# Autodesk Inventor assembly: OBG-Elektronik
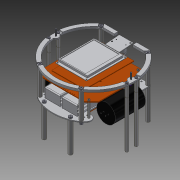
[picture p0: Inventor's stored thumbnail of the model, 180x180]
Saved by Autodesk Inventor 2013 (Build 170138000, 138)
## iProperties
Created: 2012-08
Part Number: OBG-Elektronik
Document SubType Name: Assembly
Designer: rYan
Mass: 1020.23 g
Surface Area: 2037.74 cm^2
Volume: 481.002 cm^3
Density: 2.12105 g/cm^3
Author: rYan
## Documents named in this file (23)
- D:\SVN\2013\Inventor\Elektronik\OBG-Elektronik.iam
- D:\SVN\2013\Inventor\Elektronik\Elektronikhalter.ipt
- D:\SVN\2013\Inventor\Elektronik\Kondensatorhalter.ipt
- D:\SVN\2013\Inventor\Kaufteile\Abstandsbolzen Typ A M4-65mm.ipt
- E:\Tigers SVN\mechanik\2013\Inventor\Kaufteile\Abstandsbolzen Typ A.ipt
- D:\SVN\2013\Inventor\Kaufteile\Kondensator 40x65.ipt
- D:\SVN\2013\Inventor\Kaufteile\Abstandsbolzen Typ A M2.5-20mm-SW4.ipt
- D:\SVN\2013\Inventor\Kaufteile\Abstandsbolzen Typ A M2.5-30mm-SW4.ipt
- D:\SVN\2013\Inventor\Inhaltscenter\de-DE\DIN 7984\DIN 7984 - M3 x 6.ipt
- D:\SVN\2013\Inventor\Elektronik\UBG-Mainboard.iam
- D:\SVN\2013\Inventor\Elektronik\Kickerboard.ipt
- D:\SVN\2013\Inventor\Kaufteile\Akku 2S1P.ipt
- E:\Tigers SVN\mechanik\2013\Inventor\Kaufteile\Abstandsbolzen Typ B.ipt
- D:\SVN\2013\Inventor\Ring.ipt
- D:\SVN\2013\Inventor\Kaufteile\Abstandsbolzen Typ A M3-100mm.ipt
- D:\SVN\2013\Inventor\Inhaltscenter\de-DE\DIN 7984\DIN 7984 - M3 x 16.ipt
- D:\SVN\2013\Inventor\Kaufteile\Abstandsbolzen Typ B M3-22mm.ipt
- D:\SVN\2013\Inventor\Kaufteile\Abstandsbolzen Typ B M4-55mm.ipt
- D:\SVN\2013\Inventor\Inhaltscenter\de-DE\ISO 10511\ISO 10511 - M4.ipt
- D:\SVN\2013\Inventor\Kaufteile\Abstandsbolzen Typ B M3-10mm.ipt
- D:\SVN\2013\Inventor\Inhaltscenter\en-US\DIN 7984\DIN 7984 - M4 x 6.ipt
- D:\SVN\2013\Inventor\Inhaltscenter\en-US\DIN 7984\DIN 7984 - M3 x 6.ipt
- D:\SVN\2013\Inventor\Inhaltscenter\en-US\ISO 4762(1)\ISO 4762 - M2,5 x 6DIN EN ISO.ipt
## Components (68 placed, 19 different names)
1. Elektronikhalter:1 — Passend:1, Passend:2, Passend:3, Passend:4, Passend:5, Passend:6, Passend:9, Passend:10, Passend:11, Passend:14, Passend:21, Passend:22, Passend:23, Passend:24, Passend:39, Passend:40, Passend:43, Passend:44, Passend:52, Passend:54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
2. UBG-Mainboard:1 [sub-assembly] — Passend:157, Passend:158, Passend:159, Passend:168, Passend:169, Passend:170, Passend:171
3. Kondensator 40x65:2 — Passend:16, Fluchtend:1, Fluchtend:3
4. Kondensator 40x65:1 — Passend:15, Fluchtend:1, Fluchtend:2, Fluchtend:3
5. Kickerboard:1 — Passend:102, Passend:103, Passend:104, Mate:255
6. Akku 2S1P:1 — Passend:113, Passend:114
7. Akku 2S1P:2 — Passend:115, Passend:116
8. Ring:1 — Passend:192, Passend:194, Passend:196, Passend:198, Passend:207, Passend:208, Passend:209, Passend:210, Passend:211, Passend:212, Passend:213, Passend:214, Passend:216, Passend:218, Passend:220, Passend:222, Passend:224, Passend:226, Passend:235, Passend:236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
9. DIN 7984 M3 x 16:1 — Passend:224
10. DIN 7984 M3 x 16:2 — Passend:226
11. DIN EN ISO 10511 M4:1 — Passend:243
12. DIN EN ISO 10511 M4:2 — Passend:245
13. Abstandsbolzen Typ B M3-10mm:25 — Mate:246, Mate:252
14. Abstandsbolzen Typ B M3-10mm:26 — Mate:247, Mate:253
15. Abstandsbolzen Typ B M3-10mm:27 — Mate:248, Mate:251
16. Abstandsbolzen Typ B M3-10mm:28 — Mate:249, Mate:250
17. Abstandsbolzen Typ A M4-65mm:2 — Passend:10, Passend:14, Fluchtend:6
18. Abstandsbolzen Typ A M4-65mm:4 — Passend:9, Passend:11, Fluchtend:6
19. Abstandsbolzen Typ A M4-65mm:15 — Passend:144, Passend:145, Fluchtend:7
20. Abstandsbolzen Typ A M4-65mm:16 — Passend:143, Passend:146, Fluchtend:7
21. DIN 7984 M4 x 6:5
22. DIN 7984 M4 x 6:6 — Passend:152
23. Abstandsbolzen Typ A M2.5-30mm-SW4:19 — Passend:160, Passend:163
24. DIN EN ISO 4762 M2,5 x 6:10 — Passend:169, Passend:171
25. DIN EN ISO 4762 M2,5 x 6:9 — Passend:165, Passend:166
26. Abstandsbolzen Typ A M2.5-30mm-SW4:20 — Passend:161, Passend:162
27. DIN EN ISO 4762 M2,5 x 6:8 — Passend:168, Passend:170
28. DIN EN ISO 4762 M2,5 x 6:7 — Passend:164, Passend:167
29. Abstandsbolzen Typ A M2.5-30mm-SW4:12 — Passend:40, Passend:44, Passend:112, Passend:157, Passend:159
30. DIN EN ISO 4762 M2,5 x 6:6 — Passend:54
31. DIN EN ISO 4762 M2,5 x 6:5 — Passend:112
32. Abstandsbolzen Typ A M2.5-30mm-SW4:11 — Passend:39, Passend:43, Passend:110, Passend:158
33. DIN EN ISO 4762 M2,5 x 6:4 — Passend:52
34. DIN EN ISO 4762 M2,5 x 6:3 — Passend:110
35. Abstandsbolzen Typ A M2.5-20mm-SW4:7 — Passend:22, Passend:24, Fluchtend:4, Passend:114
36. DIN EN ISO 4762 M2,5 x 6:1 — Passend:84
37. Abstandsbolzen Typ A M2.5-20mm-SW4:8 — Passend:21, Passend:23, Fluchtend:4, Passend:116
38. DIN EN ISO 4762 M2,5 x 6:2 — Passend:86
39. Kondensatorhalter:1 — Passend:4, Passend:5, Passend:6, Passend:16
40. DIN 7984 M3 x 6:2 — Passend:62
41. DIN 7984 M3 x 6:3 — Passend:64
42. Kondensatorhalter:2 — Passend:1, Passend:2, Passend:3, Passend:15, Fluchtend:2, Passend:60, Passend:62, Passend:64, Passend:70
43. DIN 7984 M3 x 6:1 — Passend:60
44. DIN 7984 M3 x 6:4 — Passend:70
45. Abstandsbolzen Typ B M4-55mm:21 — Passend:227, Passend:233, Fluchtend:15
46. Abstandsbolzen Typ B M4-55mm:22 — Passend:228, Passend:234, Fluchtend:15
47. Abstandsbolzen Typ B M4-55mm:23 — Passend:229, Passend:231, Passend:236, Passend:237, Fluchtend:14
48. Abstandsbolzen Typ B M4-55mm:24 — Passend:230, Passend:232, Passend:235, Fluchtend:14
49. DIN 7984 M4 x 6:1 — Passend:192, Passend:240
50. DIN 7984 M4 x 6:2 — Passend:194, Passend:241
51. DIN 7984 M4 x 6:3 — Passend:196, Passend:238
52. DIN 7984 M4 x 6:4 — Passend:198, Passend:239
53. Abstandsbolzen Typ B M3-22mm:13 — Passend:199, Passend:200, Fluchtend:8, Passend:207, Passend:214, Fluchtend:12
54. Abstandsbolzen Typ B M3-22mm:14 — Passend:201, Passend:202, Fluchtend:9, Passend:208, Passend:213, Fluchtend:12
55. Abstandsbolzen Typ B M3-22mm:15 — Passend:205, Passend:206, Fluchtend:11, Passend:209, Passend:212, Fluchtend:13
56. Abstandsbolzen Typ B M3-22mm:16 — Passend:203, Passend:204, Fluchtend:10, Passend:210, Passend:211, Fluchtend:13
57. Abstandsbolzen Typ A M3-100mm:23 — Passend:199, Passend:200, Fluchtend:8
58. Abstandsbolzen Typ A M3-100mm:24 — Passend:201, Passend:202, Fluchtend:9
59. Abstandsbolzen Typ A M3-100mm:25 — Passend:205, Passend:206, Fluchtend:11
60. Abstandsbolzen Typ A M3-100mm:26 — Passend:203, Passend:204, Fluchtend:10
61. DIN 7984 M3 x 6:5 — Passend:218
62. DIN 7984 M3 x 6:6 — Passend:220
63. DIN 7984 M3 x 6:7 — Passend:222
64. DIN 7984 M3 x 6:8 — Passend:216
65. DIN 7984 M3 x 6:9 — Mate:255
66. DIN 7984 M3 x 6:10
67. DIN 7984 M3 x 6:11
68. DIN 7984 M3 x 6:12
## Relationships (123: Mate 109, Flush 14)
- Passend:1 [Mate]: Elektronikhalter:1 ↔ Kondensatorhalter:2
- Passend:2 [Mate]: Elektronikhalter:1 ↔ Kondensatorhalter:2
- Passend:3 [Mate]: Elektronikhalter:1 ↔ Kondensatorhalter:2
- Passend:4 [Mate]: Elektronikhalter:1 ↔ Kondensatorhalter:1
- Passend:5 [Mate]: Elektronikhalter:1 ↔ Kondensatorhalter:1
- Passend:6 [Mate]: Elektronikhalter:1 ↔ Kondensatorhalter:1
- Passend:9 [Mate]: Elektronikhalter:1 ↔ Abstandsbolzen Typ A M4-65mm:4
- Passend:10 [Mate]: Elektronikhalter:1 ↔ Abstandsbolzen Typ A M4-65mm:2
- Passend:11 [Mate]: Elektronikhalter:1 ↔ Abstandsbolzen Typ A M4-65mm:4
- Passend:14 [Mate]: Elektronikhalter:1 ↔ Abstandsbolzen Typ A M4-65mm:2
- Passend:15 [Mate]: Kondensator 40x65:1 ↔ Kondensatorhalter:2
- Passend:16 [Mate]: Kondensator 40x65:2 ↔ Kondensatorhalter:1
- Fluchtend:1 [Flush]: Kondensator 40x65:2 ↔ Kondensator 40x65:1
- Fluchtend:2 [Flush]: Kondensator 40x65:1 ↔ Kondensatorhalter:2
- Fluchtend:3 [Flush]: Kondensator 40x65:2 ↔ Kondensator 40x65:1
- Passend:21 [Mate]: Elektronikhalter:1 ↔ Abstandsbolzen Typ A M2.5-20mm-SW4:8
- Passend:22 [Mate]: Elektronikhalter:1 ↔ Abstandsbolzen Typ A M2.5-20mm-SW4:7
- Passend:23 [Mate]: Elektronikhalter:1 ↔ Abstandsbolzen Typ A M2.5-20mm-SW4:8
- Passend:24 [Mate]: Elektronikhalter:1 ↔ Abstandsbolzen Typ A M2.5-20mm-SW4:7
- Fluchtend:4 [Flush]: Abstandsbolzen Typ A M2.5-20mm-SW4:7 ↔ Abstandsbolzen Typ A M2.5-20mm-SW4:8
- Passend:39 [Mate]: Elektronikhalter:1 ↔ Abstandsbolzen Typ A M2.5-30mm-SW4:11
- Passend:40 [Mate]: Elektronikhalter:1 ↔ Abstandsbolzen Typ A M2.5-30mm-SW4:12
- Passend:43 [Mate]: Elektronikhalter:1 ↔ Abstandsbolzen Typ A M2.5-30mm-SW4:11
- Passend:44 [Mate]: Elektronikhalter:1 ↔ Abstandsbolzen Typ A M2.5-30mm-SW4:12
- Passend:52 [Mate]: Elektronikhalter:1 ↔ DIN EN ISO 4762 M2,5 x 6:4
- Passend:54 [Mate]: Elektronikhalter:1 ↔ DIN EN ISO 4762 M2,5 x 6:6
- Passend:60 [Mate]: Kondensatorhalter:2 ↔ DIN 7984 M3 x 6:1
- Passend:62 [Mate]: DIN 7984 M3 x 6:2 ↔ Kondensatorhalter:2
- Passend:64 [Mate]: DIN 7984 M3 x 6:3 ↔ Kondensatorhalter:2
- Passend:70 [Mate]: Kondensatorhalter:2 ↔ DIN 7984 M3 x 6:4
- Passend:84 [Mate]: Elektronikhalter:1 ↔ DIN EN ISO 4762 M2,5 x 6:1
- Passend:86 [Mate]: Elektronikhalter:1 ↔ DIN EN ISO 4762 M2,5 x 6:2
- Passend:102 [Mate]: Elektronikhalter:1 ↔ Kickerboard:1
- Passend:103 [Mate]: Elektronikhalter:1 ↔ Kickerboard:1
- Passend:104 [Mate]: Elektronikhalter:1 ↔ Kickerboard:1
- Passend:110 [Mate]: Abstandsbolzen Typ A M2.5-30mm-SW4:11 ↔ DIN EN ISO 4762 M2,5 x 6:3
- Passend:112 [Mate]: Abstandsbolzen Typ A M2.5-30mm-SW4:12 ↔ DIN EN ISO 4762 M2,5 x 6:5
- Passend:113 [Mate]: Elektronikhalter:1 ↔ Akku 2S1P:1
- Passend:114 [Mate]: Akku 2S1P:1 ↔ Abstandsbolzen Typ A M2.5-20mm-SW4:7
- Passend:115 [Mate]: Elektronikhalter:1 ↔ Akku 2S1P:2
- Passend:116 [Mate]: Akku 2S1P:2 ↔ Abstandsbolzen Typ A M2.5-20mm-SW4:8
- Fluchtend:6 [Flush]: Abstandsbolzen Typ A M4-65mm:2 ↔ Abstandsbolzen Typ A M4-65mm:4
- Passend:143 [Mate]: Elektronikhalter:1 ↔ Abstandsbolzen Typ A M4-65mm:16
- Passend:144 [Mate]: Elektronikhalter:1 ↔ Abstandsbolzen Typ A M4-65mm:15
- Passend:145 [Mate]: Elektronikhalter:1 ↔ Abstandsbolzen Typ A M4-65mm:15
- Passend:146 [Mate]: Elektronikhalter:1 ↔ Abstandsbolzen Typ A M4-65mm:16
- Passend:152 [Mate]: Elektronikhalter:1 ↔ DIN 7984 M4 x 6:6
- Passend:157 [Mate]: UBG-Mainboard:1 ↔ Abstandsbolzen Typ A M2.5-30mm-SW4:12
- Passend:158 [Mate]: UBG-Mainboard:1 ↔ Abstandsbolzen Typ A M2.5-30mm-SW4:11
- Passend:159 [Mate]: UBG-Mainboard:1 ↔ Abstandsbolzen Typ A M2.5-30mm-SW4:12
- Passend:160 [Mate]: Elektronikhalter:1 ↔ Abstandsbolzen Typ A M2.5-30mm-SW4:19
- Passend:161 [Mate]: Elektronikhalter:1 ↔ Abstandsbolzen Typ A M2.5-30mm-SW4:20
- Passend:162 [Mate]: Elektronikhalter:1 ↔ Abstandsbolzen Typ A M2.5-30mm-SW4:20
- Passend:163 [Mate]: Elektronikhalter:1 ↔ Abstandsbolzen Typ A M2.5-30mm-SW4:19
- Passend:164 [Mate]: Elektronikhalter:1 ↔ DIN EN ISO 4762 M2,5 x 6:7
- Passend:165 [Mate]: Elektronikhalter:1 ↔ DIN EN ISO 4762 M2,5 x 6:9
- Passend:166 [Mate]: Elektronikhalter:1 ↔ DIN EN ISO 4762 M2,5 x 6:9
- Passend:167 [Mate]: Elektronikhalter:1 ↔ DIN EN ISO 4762 M2,5 x 6:7
- Passend:168 [Mate]: UBG-Mainboard:1 ↔ DIN EN ISO 4762 M2,5 x 6:8
- Passend:169 [Mate]: UBG-Mainboard:1 ↔ DIN EN ISO 4762 M2,5 x 6:10
- Passend:170 [Mate]: UBG-Mainboard:1 ↔ DIN EN ISO 4762 M2,5 x 6:8
- Passend:171 [Mate]: UBG-Mainboard:1 ↔ DIN EN ISO 4762 M2,5 x 6:10
- Fluchtend:7 [Flush]: Abstandsbolzen Typ A M4-65mm:15 ↔ Abstandsbolzen Typ A M4-65mm:16
- Passend:192 [Mate]: Ring:1 ↔ DIN 7984 M4 x 6:1
- Passend:194 [Mate]: Ring:1 ↔ DIN 7984 M4 x 6:2
- Passend:196 [Mate]: Ring:1 ↔ DIN 7984 M4 x 6:3
- Passend:198 [Mate]: Ring:1 ↔ DIN 7984 M4 x 6:4
- Passend:199 [Mate]: Abstandsbolzen Typ B M3-22mm:13 ↔ Abstandsbolzen Typ A M3-100mm:23
- Passend:200 [Mate]: Abstandsbolzen Typ B M3-22mm:13 ↔ Abstandsbolzen Typ A M3-100mm:23
- Fluchtend:8 [Flush]: Abstandsbolzen Typ B M3-22mm:13 ↔ Abstandsbolzen Typ A M3-100mm:23
- Passend:201 [Mate]: Abstandsbolzen Typ B M3-22mm:14 ↔ Abstandsbolzen Typ A M3-100mm:24
- Passend:202 [Mate]: Abstandsbolzen Typ B M3-22mm:14 ↔ Abstandsbolzen Typ A M3-100mm:24
- Fluchtend:9 [Flush]: Abstandsbolzen Typ B M3-22mm:14 ↔ Abstandsbolzen Typ A M3-100mm:24
- Passend:203 [Mate]: Abstandsbolzen Typ B M3-22mm:16 ↔ Abstandsbolzen Typ A M3-100mm:26
- Passend:204 [Mate]: Abstandsbolzen Typ B M3-22mm:16 ↔ Abstandsbolzen Typ A M3-100mm:26
- Fluchtend:10 [Flush]: Abstandsbolzen Typ B M3-22mm:16 ↔ Abstandsbolzen Typ A M3-100mm:26
- Passend:205 [Mate]: Abstandsbolzen Typ B M3-22mm:15 ↔ Abstandsbolzen Typ A M3-100mm:25
- Passend:206 [Mate]: Abstandsbolzen Typ B M3-22mm:15 ↔ Abstandsbolzen Typ A M3-100mm:25
- Fluchtend:11 [Flush]: Abstandsbolzen Typ B M3-22mm:15 ↔ Abstandsbolzen Typ A M3-100mm:25
- Passend:207 [Mate]: Ring:1 ↔ Abstandsbolzen Typ B M3-22mm:13
- Passend:208 [Mate]: Ring:1 ↔ Abstandsbolzen Typ B M3-22mm:14
- Passend:209 [Mate]: Ring:1 ↔ Abstandsbolzen Typ B M3-22mm:15
- Passend:210 [Mate]: Ring:1 ↔ Abstandsbolzen Typ B M3-22mm:16
- Passend:211 [Mate]: Ring:1 ↔ Abstandsbolzen Typ B M3-22mm:16
- Passend:212 [Mate]: Ring:1 ↔ Abstandsbolzen Typ B M3-22mm:15
- Passend:213 [Mate]: Ring:1 ↔ Abstandsbolzen Typ B M3-22mm:14
- Passend:214 [Mate]: Ring:1 ↔ Abstandsbolzen Typ B M3-22mm:13
- Fluchtend:12 [Flush]: Abstandsbolzen Typ B M3-22mm:13 ↔ Abstandsbolzen Typ B M3-22mm:14
- Fluchtend:13 [Flush]: Abstandsbolzen Typ B M3-22mm:15 ↔ Abstandsbolzen Typ B M3-22mm:16
- Passend:216 [Mate]: Ring:1 ↔ DIN 7984 M3 x 6:8
- Passend:218 [Mate]: Ring:1 ↔ DIN 7984 M3 x 6:5
- Passend:220 [Mate]: Ring:1 ↔ DIN 7984 M3 x 6:6
- Passend:222 [Mate]: Ring:1 ↔ DIN 7984 M3 x 6:7
- Passend:224 [Mate]: Ring:1 ↔ DIN 7984 M3 x 16:1
- Passend:226 [Mate]: Ring:1 ↔ DIN 7984 M3 x 16:2
- Passend:227 [Mate]: Elektronikhalter:1 ↔ Abstandsbolzen Typ B M4-55mm:21
- Passend:228 [Mate]: Elektronikhalter:1 ↔ Abstandsbolzen Typ B M4-55mm:22
- Passend:229 [Mate]: Elektronikhalter:1 ↔ Abstandsbolzen Typ B M4-55mm:23
- Passend:230 [Mate]: Elektronikhalter:1 ↔ Abstandsbolzen Typ B M4-55mm:24
- Passend:231 [Mate]: Elektronikhalter:1 ↔ Abstandsbolzen Typ B M4-55mm:23
- Passend:232 [Mate]: Elektronikhalter:1 ↔ Abstandsbolzen Typ B M4-55mm:24
- Passend:233 [Mate]: Elektronikhalter:1 ↔ Abstandsbolzen Typ B M4-55mm:21
- Passend:234 [Mate]: Elektronikhalter:1 ↔ Abstandsbolzen Typ B M4-55mm:22
- Passend:235 [Mate]: Ring:1 ↔ Abstandsbolzen Typ B M4-55mm:24
- Passend:236 [Mate]: Ring:1 ↔ Abstandsbolzen Typ B M4-55mm:23
- Passend:237 [Mate]: Ring:1 ↔ Abstandsbolzen Typ B M4-55mm:23
- Passend:238 [Mate]: Ring:1 ↔ DIN 7984 M4 x 6:3
- Passend:239 [Mate]: Ring:1 ↔ DIN 7984 M4 x 6:4
- Passend:240 [Mate]: Ring:1 ↔ DIN 7984 M4 x 6:1
- Passend:241 [Mate]: Ring:1 ↔ DIN 7984 M4 x 6:2
- Fluchtend:14 [Flush]: Abstandsbolzen Typ B M4-55mm:23 ↔ Abstandsbolzen Typ B M4-55mm:24
- Fluchtend:15 [Flush]: Abstandsbolzen Typ B M4-55mm:21 ↔ Abstandsbolzen Typ B M4-55mm:22
- Passend:243 [Mate]: Elektronikhalter:1 ↔ DIN EN ISO 10511 M4:1
- Passend:245 [Mate]: Elektronikhalter:1 ↔ DIN EN ISO 10511 M4:2
- Mate:246: Elektronikhalter:1 ↔ Abstandsbolzen Typ B M3-10mm:25
- Mate:247: Elektronikhalter:1 ↔ Abstandsbolzen Typ B M3-10mm:26
- Mate:248: Elektronikhalter:1 ↔ Abstandsbolzen Typ B M3-10mm:27
- Mate:249: Elektronikhalter:1 ↔ Abstandsbolzen Typ B M3-10mm:28
- Mate:250: Elektronikhalter:1 ↔ Abstandsbolzen Typ B M3-10mm:28
- Mate:251: Elektronikhalter:1 ↔ Abstandsbolzen Typ B M3-10mm:27
- Mate:252: Elektronikhalter:1 ↔ Abstandsbolzen Typ B M3-10mm:25
- Mate:253: Elektronikhalter:1 ↔ Abstandsbolzen Typ B M3-10mm:26
- Mate:255: Kickerboard:1 ↔ DIN 7984 M3 x 6:9
